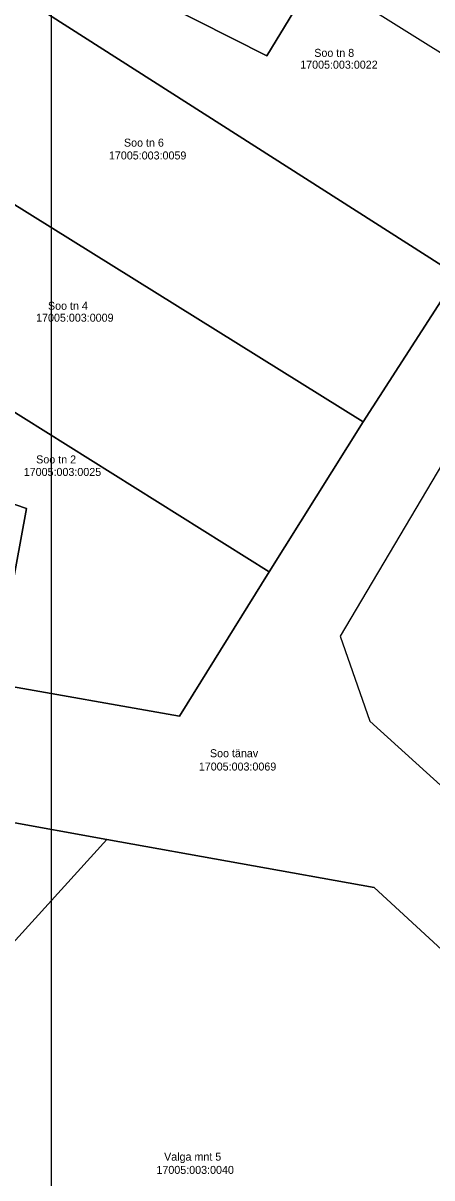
# Model space of a CAD drawing. Extents: x 640876 to 641418, y 6455595 to 6456085.
# Drawn here: x 641253.1 to 641299, y 6455847.2 to 6455977.1 of the extents above; entities that cross this region are included whole.
import ezdxf

# ---------------------------------------------------------------- set-up
doc = ezdxf.new("R2010")
doc.units = 0
doc.layers.add('PIIR', color=7, linetype='Continuous')
doc.layers.add('VORMISTUS', color=7, linetype='Continuous')

msp = doc.modelspace()

# ---------------------------------------------------------------- linework, layer by layer
at = {"layer": 'PIIR'}
for points in [[(641237.36, 6455995.24), (641241.97, 6456004.88), (641289.46, 6456006.95), (641298.39, 6456002.93), (641286.06, 6455982.56), (641280.5, 6455973.42)], [(641301.94, 6455948.72), (641235.34, 6455991.29), (641237.36, 6455995.24), (641280.5, 6455973.42), (641286.06, 6455982.56), (641312.6, 6455965.93)], [(641301.94, 6455948.72), (641291.33, 6455932.26), (641228.11, 6455971.68), (641235.34, 6455991.29)], [(641280.77, 6455915.37), (641220.5, 6455953.19), (641228.11, 6455971.68), (641291.33, 6455932.26)], [(641270.69, 6455899.15), (641249.88, 6455902.84), (641253.51, 6455922.51), (641213.41, 6455936.25), (641220.5, 6455953.19), (641280.77, 6455915.37)], [(641201.58, 6455908.74), (641213.41, 6455936.25), (641253.51, 6455922.51), (641249.88, 6455902.84)], [(641239.33, 6455889.47), (641262.53, 6455885.29), (641239.42, 6455859.81), (641224.6, 6455873.24)], [(641270.46, 6455810.04), (641229.68, 6455849.06), (641239.42, 6455859.81), (641262.53, 6455885.29), (641292.55, 6455879.89), (641315.35, 6455858.84)]]:
    msp.add_lwpolyline(points, close=True, dxfattribs=at)
for points in [[(641313.65, 6455950.2), (641288.74, 6455908.14), (641292.09, 6455898.6), (641325.05, 6455868.67)], [(641315.35, 6455858.84), (641292.55, 6455879.89), (641262.53, 6455885.29), (641239.33, 6455889.47), (641203.18, 6455849.61), (641191.84, 6455860.59), (641224.93, 6455905.88), (641249.88, 6455902.84), (641270.69, 6455899.15), (641280.77, 6455915.37), (641291.33, 6455932.26), (641301.94, 6455948.72)]]:
    msp.add_lwpolyline(points, dxfattribs=at)
at = {"layer": 'VORMISTUS'}
msp.add_line((641256.3, 6455709.6), (641256.3, 6456020.09), dxfattribs=at)

# ---------------------------------------------------------------- texts
at = {"layer": 'PIIR'}
for s, p in [('Soo tn 8', (641285.83, 6455973.31)), ('17005:003:0022', (641284.25, 6455971.98)), ('Soo tn 6', (641264.45, 6455963.21)), ('17005:003:0059', (641262.76, 6455961.77)), ('Soo tn 4', (641255.91, 6455944.86)), ('17005:003:0009', (641254.58, 6455943.52)), ('Soo tn 2', (641254.59, 6455927.58)), ('Soo tänav', (641274.11, 6455894.53)), ('17005:003:0069', (641272.86, 6455893.03)), ('Valga mnt 5', (641268.96, 6455849.15)), ('17005:003:0040', (641268.1, 6455847.66))]:
    msp.add_text(s, height=0.9, dxfattribs=at).set_placement(p)
msp.add_text('17005:003:0025', height=0.9, rotation=360, dxfattribs=at).set_placement((641253.19, 6455926.17))

doc.saveas('drawing.dxf')
